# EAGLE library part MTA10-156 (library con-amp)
AMP connector
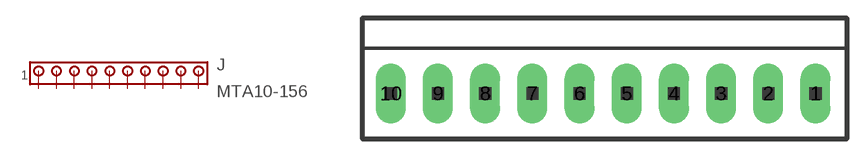
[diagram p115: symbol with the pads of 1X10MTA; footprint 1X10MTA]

Designator prefix J

## MTA10-156 (OC_FARNELL: unknown; OC_NEWARK: unknown)  [1X10MTA]
1  1  pas
2  2  pas
3  3  pas
4  4  pas
5  5  pas
6  6  pas
7  7  pas
8  8  pas
9  9  pas
10  10  pas

## Footprint 1X10MTA (pad centres in mm)
AMP MTA connector
drill 1.676 long: 1 17.831,0; 2 13.868,0; 3 9.906,0; 4 5.944,0; 5 1.981,0; 6 -1.981,0; 7 -5.944,0; 8 -9.906,0; 9 -13.868,0; 10 -17.831,0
